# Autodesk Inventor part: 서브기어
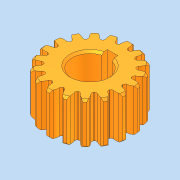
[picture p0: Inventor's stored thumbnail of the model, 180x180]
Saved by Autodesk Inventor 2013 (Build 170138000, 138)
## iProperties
Company: 한국ATC센터
Created: 2014-12
Part Number: 서브기어
Document SubType Name: Modeling
Designer: KYOUNG IL JANG
Density: 1 g/cm^3
Mass: 15.166 g
Surface Area: 69.6172 cm^2
Volume: 15.166 cm^3
Material: 일반
Author: KYOUNG IL JANG
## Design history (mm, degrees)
sketch "스케치1"
  geometry: C1 r 15.5 at (0, 0); A1 r 1.155 centre (-2.906, 16.386) between (-2.542, 15.29) and (-1.751, 16.378); A2 r 5.602 centre (3.849, 16.522) between (-1.326, 18.666) and (-1.751, 16.378); A3 r 9.354 centre (7.378, 15.24) between (-0.682, 19.988) and (-1.326, 18.666); A4 r 1.155 centre (2.906, 16.386) between (1.751, 16.378) and (2.542, 15.29); A5 r 5.602 centre (-3.849, 16.522) between (1.751, 16.378) and (1.326, 18.666); A6 r 9.354 centre (-7.378, 15.24) between (1.326, 18.666) and (0.682, 19.988); A7 r 20 centre (0, 0) between (0.682, 19.988) and (-0.682, 19.988); A8 r 15.5 centre (0, 0) between (2.542, 15.29) and (-2.542, 15.29); 1 further point
  constraints: 16 point on circle, 9 centre point, 2 coincident
extrude "돌출1" new body sketch "스케치1" stored distance "d0" = 20; taper "d1" = 0 deg
extrude "돌출2" join sketch "스케치1" stored distance "d2" = 20; taper "d3" = 0 deg
chamfer "모따기1" distance "d4" = 1; stored, may be unused: second distance "d5" = 2, angle "d6" = 45 deg
hole "구멍1" diameter "d12" = 17; stored, may be unused: countersink angle "d16" = 90 deg, drill point angle "d18" = 118 deg; dims "d10" = 10, "d11" = 10, "d13" = 6, "d14" = 4, "d15" = 2, "d17" = 8
sketch "스케치2"
  geometry: L1 (-2.5, 8.124)-(-2.5, 10.8); L2 (-2.5, 10.8)-(2.5, 10.8); L3 (2.5, 10.8)-(2.5, 8.124); A1 r 8.5 centre (0, 0) between (-2.5, 8.124) and (2.5, 8.124) reference; 1 further point
  constraints: 6 end point, 2 parallel, 2 point on circle, 1 horizontal, 1 vertical
  dimensions: "d22" = 5 distance of L1.end L2.end; "d23" = 2.3 distance edge to line of A1 L2
extrude "돌출3" cut sketch "스케치2" stored distance "d24" = 20; taper "d25" = 0 deg
chamfer "모따기2" distance "d19" = 1; stored, may be unused: second distance "d20" = 2, angle "d21" = 45 deg
node "솔리드1"
pattern_circular "원형 패턴1" dims angle "d8" = 360 deg
